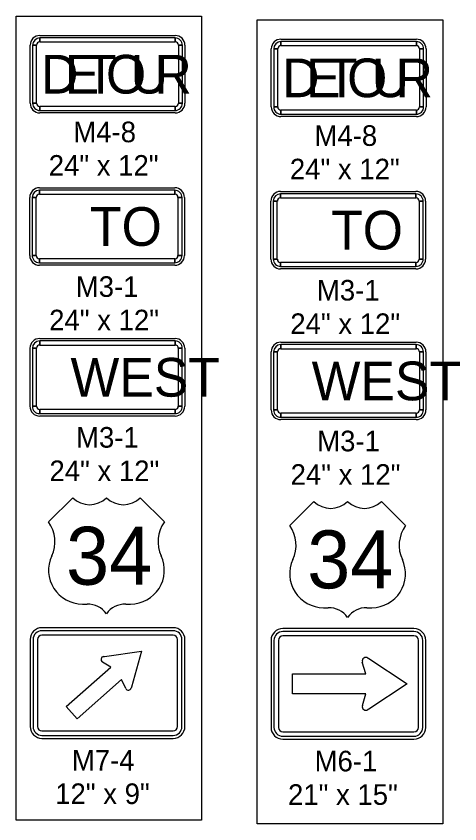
# Model space of a CAD drawing. Extents: x 10133 to 81668, y 6132 to 11018.
# Drawn here: x 11555.9 to 11728.4, y 6710.3 to 7024 of the extents above; entities that cross this region are included whole.
import ezdxf

# ---------------------------------------------------------------- set-up
doc = ezdxf.new("R2010")
doc.units = 0
for name, color, linetype in [('dsnTextFinalPlan', 7, 'Continuous'), ('Level 10', 7, 'Continuous'), ('Level 4', 7, 'Continuous'), ('Level 5', 7, 'Continuous')]:
    doc.layers.add(name, color=color, linetype=linetype)

msp = doc.modelspace()

# ---------------------------------------------------------------- linework, layer by layer
at = {"layer": 'dsnTextFinalPlan'}
for p, q in [((11616.94, 6786.48), (11565.97, 6786.48)), ((11561.39, 6781.9), (11561.39, 6748.11)), ((11621.52, 6748.11), (11621.52, 6781.9)), ((11565.97, 6743.53), (11616.94, 6743.53))]:
    msp.add_line(p, q, dxfattribs=at)
for points in [[(11555.92, 7023.97), (11627.99, 7023.97), (11627.99, 6711.75), (11555.92, 6711.75)], [(11649.64, 7022.55), (11721.71, 7022.55), (11721.71, 6710.33), (11649.64, 6710.33)]]:
    msp.add_lwpolyline(points, close=True, dxfattribs=at)
for points in [[(11590.24, 6775.34), (11604.6, 6777.41), (11600.75, 6763.44)], [(11598.53, 6762.92), (11596.91, 6766.43), (11579.58, 6751.15), (11575.43, 6755.86), (11592.75, 6771.14), (11589.46, 6773.17)]]:
    msp.add_lwpolyline(points, dxfattribs=at)
for centre, radius, start, end in [((11565.97, 6781.9), 4.58, 90, 180), ((11616.94, 6781.9), 4.58, 360, 90), ((11590.08, 6774.15), 1.16, 98.0346, 237.3927), ((11573.71, 6890.12), 115.96, 278.0346, 278.1951), ((11599.56, 6763.41), 1.14, 205.4546, 344.7341), ((11712.53, 6732.58), 115.96, 164.5667, 164.7341), ((11565.97, 6748.11), 4.58, 180, 270), ((11616.94, 6748.11), 4.58, 270, 0)]:
    msp.add_arc(centre, radius, start, end, dxfattribs=at)
at = {"layer": 'Level 10'}
for p, q in [((11565.13, 7016.46), (11617.74, 7016.46)), ((11565.13, 7013.95), (11565.13, 7015.52)), ((11617.74, 7015.52), (11617.74, 7013.95)), ((11658.85, 7015.04), (11711.46, 7015.04)), ((11658.85, 7012.54), (11658.85, 7014.1)), ((11711.46, 7014.1), (11711.46, 7012.54)), ((11561.37, 6990.15), (11561.37, 7012.7)), ((11562.31, 7012.7), (11563.88, 7012.7)), ((11619, 7012.7), (11620.56, 7012.7)), ((11621.5, 7012.7), (11621.5, 6990.15)), ((11655.09, 6988.73), (11655.09, 7011.28)), ((11656.03, 7011.28), (11657.6, 7011.28)), ((11712.72, 7011.28), (11714.28, 7011.28)), ((11715.22, 7011.28), (11715.22, 6988.73)), ((11563.88, 6990.15), (11562.31, 6990.15)), ((11565.13, 6987.33), (11565.13, 6988.9)), ((11617.74, 6988.9), (11617.74, 6987.33)), ((11620.56, 6990.15), (11619, 6990.15)), ((11657.6, 6988.73), (11656.03, 6988.73)), ((11714.28, 6988.73), (11712.72, 6988.73)), ((11617.74, 6986.4), (11565.13, 6986.4)), ((11658.85, 6985.92), (11658.85, 6987.48)), ((11711.46, 6984.98), (11658.85, 6984.98)), ((11711.46, 6987.48), (11711.46, 6985.92)), ((11564.97, 6957.32), (11617.58, 6957.32)), ((11561.21, 6931.01), (11561.21, 6953.56)), ((11562.15, 6953.56), (11563.72, 6953.56)), ((11564.97, 6954.81), (11564.97, 6956.38)), ((11617.58, 6956.38), (11617.58, 6954.81)), ((11618.83, 6953.56), (11620.4, 6953.56)), ((11621.34, 6953.56), (11621.34, 6931.01)), ((11658.69, 6955.9), (11711.3, 6955.9)), ((11658.69, 6953.39), (11658.69, 6954.96)), ((11711.3, 6954.96), (11711.3, 6953.39)), ((11654.93, 6929.59), (11654.93, 6952.14)), ((11655.87, 6952.14), (11657.43, 6952.14)), ((11712.55, 6952.14), (11714.12, 6952.14)), ((11715.06, 6952.14), (11715.06, 6929.59)), ((11563.72, 6931.01), (11562.15, 6931.01)), ((11564.97, 6928.19), (11564.97, 6929.76)), ((11617.58, 6929.76), (11617.58, 6928.19)), ((11620.4, 6931.01), (11618.83, 6931.01)), ((11657.43, 6929.59), (11655.87, 6929.59)), ((11658.69, 6926.77), (11658.69, 6928.34)), ((11711.3, 6928.34), (11711.3, 6926.77)), ((11714.12, 6929.59), (11712.55, 6929.59)), ((11617.58, 6927.25), (11564.97, 6927.25)), ((11711.3, 6925.83), (11658.69, 6925.83)), ((11565.07, 6898.77), (11617.69, 6898.77)), ((11565.07, 6896.26), (11565.07, 6897.83)), ((11617.69, 6897.83), (11617.69, 6896.26)), ((11658.79, 6897.35), (11711.41, 6897.35)), ((11561.32, 6872.46), (11561.32, 6895.01)), ((11562.26, 6895.01), (11563.82, 6895.01)), ((11618.94, 6895.01), (11620.51, 6895.01)), ((11621.44, 6895.01), (11621.44, 6872.46)), ((11658.79, 6894.84), (11658.79, 6896.41)), ((11711.41, 6896.41), (11711.41, 6894.84)), ((11655.04, 6871.04), (11655.04, 6893.59)), ((11655.97, 6893.59), (11657.54, 6893.59)), ((11712.66, 6893.59), (11714.22, 6893.59)), ((11715.16, 6893.59), (11715.16, 6871.04)), ((11563.82, 6872.46), (11562.26, 6872.46)), ((11620.51, 6872.46), (11618.94, 6872.46)), ((11565.07, 6869.64), (11565.07, 6871.21)), ((11617.69, 6871.21), (11617.69, 6869.64)), ((11657.54, 6871.04), (11655.97, 6871.04)), ((11658.79, 6868.22), (11658.79, 6869.79)), ((11711.41, 6869.79), (11711.41, 6868.22)), ((11714.22, 6871.04), (11712.66, 6871.04)), ((11617.69, 6868.7), (11565.07, 6868.7)), ((11711.41, 6867.29), (11658.79, 6867.29)), ((11616.94, 6785.34), (11565.97, 6785.34)), ((11710.54, 6786.16), (11659.57, 6786.16)), ((11710.54, 6785.02), (11659.57, 6785.02)), ((11562.54, 6781.9), (11562.54, 6748.11)), ((11564.26, 6781.9), (11564.26, 6748.11)), ((11616.94, 6783.62), (11565.97, 6783.62)), ((11618.66, 6748.11), (11618.66, 6781.9)), ((11620.38, 6748.11), (11620.38, 6781.9)), ((11654.99, 6781.58), (11654.99, 6747.8)), ((11656.13, 6781.58), (11656.13, 6747.8)), ((11657.85, 6781.58), (11657.85, 6747.8)), ((11710.54, 6783.3), (11659.57, 6783.3)), ((11712.25, 6747.8), (11712.25, 6781.58)), ((11713.97, 6747.8), (11713.97, 6781.58)), ((11715.12, 6747.8), (11715.12, 6781.58)), ((11565.97, 6746.39), (11616.94, 6746.39)), ((11565.97, 6744.68), (11616.94, 6744.68)), ((11659.57, 6746.08), (11710.54, 6746.08)), ((11659.57, 6744.36), (11710.54, 6744.36)), ((11659.57, 6743.21), (11710.54, 6743.21))]:
    msp.add_line(p, q, dxfattribs=at)
for points in [[(11617.74, 7015.52), (11565.13, 7015.52), (11565.13, 7013.95), (11617.74, 7013.95), (11617.74, 7015.52)], [(11711.46, 7014.1), (11658.85, 7014.1), (11658.85, 7012.54), (11711.46, 7012.54), (11711.46, 7014.1)], [(11562.31, 7012.7), (11562.31, 6990.15), (11563.88, 6990.15), (11563.88, 7012.7), (11562.31, 7012.7)], [(11620.56, 6990.15), (11620.56, 7012.7), (11619, 7012.7), (11619, 6990.15), (11620.56, 6990.15)], [(11656.03, 7011.28), (11656.03, 6988.73), (11657.6, 6988.73), (11657.6, 7011.28), (11656.03, 7011.28)], [(11714.28, 6988.73), (11714.28, 7011.28), (11712.72, 7011.28), (11712.72, 6988.73), (11714.28, 6988.73)], [(11565.13, 6987.33), (11617.74, 6987.33), (11617.74, 6988.9), (11565.13, 6988.9), (11565.13, 6987.33)], [(11658.85, 6985.92), (11711.46, 6985.92), (11711.46, 6987.48), (11658.85, 6987.48), (11658.85, 6985.92)], [(11562.15, 6953.56), (11562.15, 6931.01), (11563.72, 6931.01), (11563.72, 6953.56), (11562.15, 6953.56)], [(11617.58, 6956.38), (11564.97, 6956.38), (11564.97, 6954.81), (11617.58, 6954.81), (11617.58, 6956.38)], [(11620.4, 6931.01), (11620.4, 6953.56), (11618.83, 6953.56), (11618.83, 6931.01), (11620.4, 6931.01)], [(11711.3, 6954.96), (11658.69, 6954.96), (11658.69, 6953.39), (11711.3, 6953.39), (11711.3, 6954.96)], [(11655.87, 6952.14), (11655.87, 6929.59), (11657.43, 6929.59), (11657.43, 6952.14), (11655.87, 6952.14)], [(11714.12, 6929.59), (11714.12, 6952.14), (11712.55, 6952.14), (11712.55, 6929.59), (11714.12, 6929.59)], [(11564.97, 6928.19), (11617.58, 6928.19), (11617.58, 6929.76), (11564.97, 6929.76), (11564.97, 6928.19)], [(11658.69, 6926.77), (11711.3, 6926.77), (11711.3, 6928.34), (11658.69, 6928.34), (11658.69, 6926.77)], [(11617.69, 6897.83), (11565.07, 6897.83), (11565.07, 6896.26), (11617.69, 6896.26), (11617.69, 6897.83)], [(11562.26, 6895.01), (11562.26, 6872.46), (11563.82, 6872.46), (11563.82, 6895.01), (11562.26, 6895.01)], [(11620.51, 6872.46), (11620.51, 6895.01), (11618.94, 6895.01), (11618.94, 6872.46), (11620.51, 6872.46)], [(11711.41, 6896.41), (11658.79, 6896.41), (11658.79, 6894.84), (11711.41, 6894.84), (11711.41, 6896.41)], [(11655.97, 6893.59), (11655.97, 6871.04), (11657.54, 6871.04), (11657.54, 6893.59), (11655.97, 6893.59)], [(11714.22, 6871.04), (11714.22, 6893.59), (11712.66, 6893.59), (11712.66, 6871.04), (11714.22, 6871.04)], [(11565.07, 6869.64), (11617.69, 6869.64), (11617.69, 6871.21), (11565.07, 6871.21), (11565.07, 6869.64)], [(11658.79, 6868.22), (11711.41, 6868.22), (11711.41, 6869.79), (11658.79, 6869.79), (11658.79, 6868.22)]]:
    msp.add_lwpolyline(points, close=True, dxfattribs=at)
for points in [[(11690.5, 6756.23), (11691.87, 6760.81), (11663.34, 6760.81), (11663.34, 6768.57), (11691.87, 6768.57), (11690.47, 6773.14)], [(11692.97, 6774.51), (11707.96, 6764.69), (11692.97, 6754.9)]]:
    msp.add_lwpolyline(points, dxfattribs=at)
for centre, radius, start, end in [((11565.13, 7012.7), 3.76, 90, 180), ((11617.74, 7012.7), 3.76, 0, 90), ((11565.13, 7012.7), 2.82, 90.0002, 179.9998), ((11565.13, 7012.7), 1.25, 90.0002, 179.9998), ((11617.74, 7012.7), 2.82, 0, 90.0002), ((11617.74, 7012.7), 1.25, 0, 90.0002), ((11658.85, 7011.28), 3.76, 90, 180), ((11658.85, 7011.28), 2.82, 90.0002, 179.9998), ((11711.46, 7011.28), 3.76, 0, 90), ((11711.46, 7011.28), 2.82, 0, 90.0002), ((11658.85, 7011.28), 1.25, 90.0002, 179.9998), ((11711.46, 7011.28), 1.25, 0, 90.0002), ((11565.13, 6990.15), 3.76, 180, 270), ((11565.13, 6990.15), 2.82, 179.9998, 270.0001), ((11565.13, 6990.15), 1.25, 179.9998, 270.0001), ((11617.74, 6990.15), 2.82, 270.0001, 0.0003), ((11617.74, 6990.15), 1.25, 270.0001, 0.0003), ((11617.74, 6990.15), 3.76, 270, 359.9911), ((11658.85, 6988.73), 3.76, 180, 270), ((11658.85, 6988.73), 2.82, 179.9998, 270.0001), ((11658.85, 6988.73), 1.25, 179.9998, 270.0001), ((11711.46, 6988.73), 2.82, 270.0001, 0.0003), ((11711.46, 6988.73), 1.25, 270.0001, 0.0003), ((11711.46, 6988.73), 3.76, 270, 359.9911), ((11564.97, 6953.56), 3.76, 90, 180), ((11617.58, 6953.56), 3.76, 0, 90), ((11564.97, 6953.56), 2.82, 90.0002, 179.9998), ((11564.97, 6953.56), 1.25, 90.0002, 179.9998), ((11617.58, 6953.56), 2.82, 0, 90.0002), ((11617.58, 6953.56), 1.25, 0, 90.0002), ((11658.69, 6952.14), 3.76, 90, 180), ((11658.69, 6952.14), 2.82, 90.0002, 179.9998), ((11711.3, 6952.14), 3.76, 0, 90), ((11711.3, 6952.14), 2.82, 0, 90.0002), ((11658.69, 6952.14), 1.25, 90.0002, 179.9998), ((11711.3, 6952.14), 1.25, 0, 90.0002), ((11564.97, 6931.01), 3.76, 180, 270), ((11564.97, 6931.01), 2.82, 179.9998, 270.0001), ((11564.97, 6931.01), 1.25, 179.9998, 270.0001), ((11617.58, 6931.01), 2.82, 270.0001, 0.0003), ((11617.58, 6931.01), 1.25, 270.0001, 0.0003), ((11617.58, 6931.01), 3.76, 270, 359.9911), ((11658.69, 6929.59), 3.76, 180, 270), ((11658.69, 6929.59), 2.82, 179.9998, 270.0001), ((11658.69, 6929.59), 1.25, 179.9998, 270.0001), ((11711.3, 6929.59), 2.82, 270.0001, 0.0003), ((11711.3, 6929.59), 1.25, 270.0001, 0.0003), ((11711.3, 6929.59), 3.76, 270, 359.9911), ((11565.07, 6895.01), 3.76, 90, 180), ((11565.07, 6895.01), 2.82, 90.0002, 179.9998), ((11617.69, 6895.01), 3.76, 0, 90), ((11617.69, 6895.01), 2.82, 0, 90.0002), ((11658.79, 6893.59), 3.76, 90, 180), ((11711.41, 6893.59), 3.76, 0, 90), ((11565.07, 6895.01), 1.25, 90.0002, 179.9998), ((11617.69, 6895.01), 1.25, 0, 90.0002), ((11658.79, 6893.59), 2.82, 90.0002, 179.9998), ((11658.79, 6893.59), 1.25, 90.0002, 179.9998), ((11711.41, 6893.59), 2.82, 0, 90.0002), ((11711.41, 6893.59), 1.25, 0, 90.0002), ((11565.07, 6872.46), 3.76, 180, 270), ((11565.07, 6872.46), 2.82, 179.9998, 270.0001), ((11565.07, 6872.46), 1.25, 179.9998, 270.0001), ((11617.69, 6872.46), 2.82, 270.0001, 0.0003), ((11617.69, 6872.46), 1.25, 270.0001, 0.0003), ((11617.69, 6872.46), 3.76, 270, 359.9911), ((11658.79, 6871.04), 3.76, 180, 270), ((11658.79, 6871.04), 2.82, 179.9998, 270.0001), ((11658.79, 6871.04), 1.25, 179.9998, 270.0001), ((11711.41, 6871.04), 2.82, 270.0001, 0.0003), ((11711.41, 6871.04), 1.25, 270.0001, 0.0003), ((11711.41, 6871.04), 3.76, 270, 359.9911), ((11565.97, 6781.9), 3.44, 90, 180), ((11616.94, 6781.9), 3.44, 0, 90), ((11659.57, 6781.58), 4.58, 90, 180), ((11659.57, 6781.58), 3.44, 90, 180), ((11710.54, 6781.58), 4.58, 360, 90), ((11710.54, 6781.58), 3.44, 0, 90), ((11565.97, 6781.9), 1.72, 90, 180), ((11616.94, 6781.9), 1.72, 0, 90), ((11659.57, 6781.58), 1.72, 90, 180), ((11710.54, 6781.58), 1.72, 0, 90), ((11691.85, 6773.53), 1.43, 56.6109, 195.9691), ((11771.42, 6894.26), 143.16, 236.6109, 236.7714), ((11691.85, 6755.85), 1.4, 164.0309, 303.3104), ((11771.24, 6635.03), 143.16, 123.143, 123.3104), ((11565.97, 6748.11), 3.44, 180, 270), ((11565.97, 6748.11), 1.72, 180, 270), ((11616.94, 6748.11), 3.44, 270, 360), ((11616.94, 6748.11), 1.72, 270, 0), ((11659.57, 6747.8), 4.58, 180, 270), ((11659.57, 6747.8), 3.44, 180, 270), ((11659.57, 6747.8), 1.72, 180, 270), ((11710.54, 6747.8), 4.58, 270, 0), ((11710.54, 6747.8), 3.44, 270, 360), ((11710.54, 6747.8), 1.72, 270, 0)]:
    msp.add_arc(centre, radius, start, end, dxfattribs=at)
at = {"layer": 'Level 4'}
for p, q in [((11577.91, 6836.93), (11568.53, 6827.56)), ((11613.53, 6827.56), (11604.16, 6836.93)), ((11671.63, 6835.52), (11662.25, 6826.14)), ((11707.25, 6826.14), (11697.88, 6835.52)), ((11581.66, 6795.68), (11583.53, 6795.68)), ((11598.53, 6795.68), (11600.41, 6795.68)), ((11675.38, 6794.27), (11677.25, 6794.27)), ((11692.25, 6794.27), (11694.13, 6794.27))]:
    msp.add_line(p, q, dxfattribs=at)
for centre, radius, start, end in [((11584.47, 6843.63), 9.38, 225.5729, 314.4272), ((11597.6, 6843.63), 9.38, 225.5729, 314.4272), ((11678.19, 6842.21), 9.38, 225.5729, 314.4272), ((11691.32, 6842.21), 9.38, 225.5729, 314.4272), ((11557.87, 6819.91), 13.13, 334.9895, 35.6629), ((11624.2, 6819.91), 13.13, 144.3372, 205.01), ((11651.59, 6818.49), 13.13, 334.9895, 35.6629), ((11717.92, 6818.49), 13.13, 144.3372, 205.01), ((11581.66, 6808.81), 13.13, 154.9897, 270.0001), ((11600.41, 6808.81), 13.13, 270.0001, 25.0104), ((11675.38, 6807.39), 13.13, 154.9897, 270.0001), ((11694.13, 6807.39), 13.13, 270.0001, 25.0104), ((11583.53, 6786.31), 9.38, 36.8699, 90.0002), ((11598.53, 6786.31), 9.38, 90.0002, 143.13), ((11677.25, 6784.89), 9.38, 36.8699, 90.0002), ((11692.25, 6784.89), 9.38, 90.0002, 143.13)]:
    msp.add_arc(centre, radius, start, end, dxfattribs=at)

# ---------------------------------------------------------------- texts
at = {"layer": 'Level 10'}
for s, height, p in [('D', 15.03, (11565.62, 6993.91)), ('E', 15.03, (11574.85, 6993.91)), ('T', 15.03, (11582.63, 6993.91)), ('O', 15.03, (11590.84, 6993.91)), ('U', 15.03, (11600.43, 6993.91)), ('R', 15.03, (11609.67, 6993.91)), ('D', 15.03, (11659.34, 6992.49)), ('E', 15.03, (11668.57, 6992.49)), ('T', 15.03, (11676.35, 6992.49)), ('O', 15.03, (11684.56, 6992.49)), ('U', 15.03, (11694.15, 6992.49)), ('R', 15.03, (11703.39, 6992.49)), ('TO', 15.032, (11584.63, 6934.77)), ('TO', 15.032, (11678.35, 6933.35)), ('WEST', 15.032, (11577.05, 6876.22)), ('WEST', 15.032, (11670.77, 6874.8))]:
    msp.add_text(s, height=height, dxfattribs=at).set_placement(p)
at = {"layer": 'Level 4'}
for p in [(11575.33, 6803.18), (11669.05, 6801.77)]:
    msp.add_text('34', height=22.5, dxfattribs=at).set_placement(p)
at = {"layer": 'Level 5'}
for s, p in [('M4-8', (11578.14, 6975.01)), ('M4-8', (11671.86, 6973.59)), ('24" x 12"', (11568.59, 6962.01)), ('24" x 12"', (11662.31, 6960.59)), ('M3-1', (11579.09, 6914.96)), ('M3-1', (11672.81, 6913.54)), ('24" x 12"', (11568.76, 6901.96)), ('24" x 12"', (11662.48, 6900.54)), ('M3-1', (11579.2, 6856.41)), ('M3-1', (11672.92, 6854.99)), ('24" x 12"', (11568.87, 6843.41)), ('24" x 12"', (11662.59, 6841.99)), ('M7-4', (11577.57, 6731.02)), ('M6-1', (11671.92, 6730.7)), ('12" x 9"', (11571.1, 6718.02)), ('21" x 15"', (11661.58, 6717.7))]:
    msp.add_text(s, height=8, dxfattribs=at).set_placement(p)

doc.saveas('drawing.dxf')
